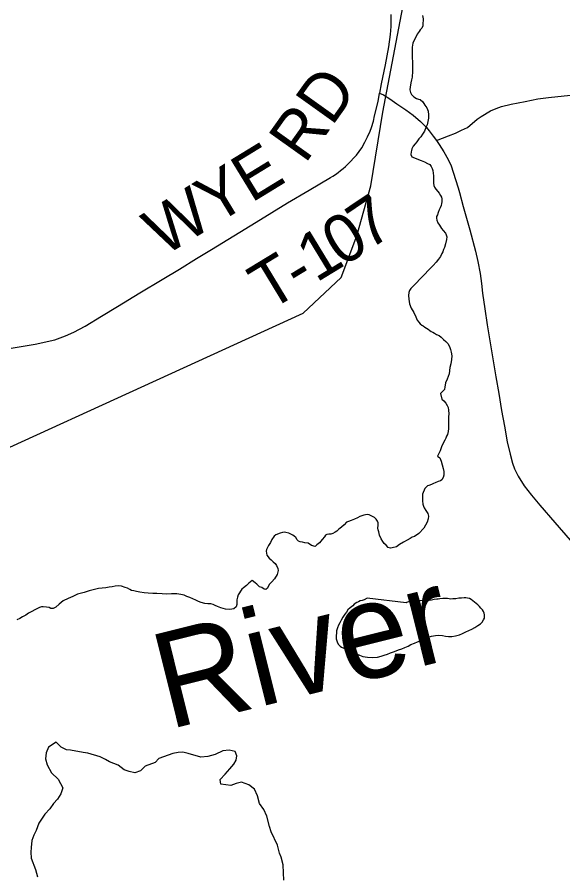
# Model space of a CAD drawing. Extents: x 103424 to 286016, y 38711 to 110967.
# Drawn here: x 125931 to 129380, y 73362 to 78769 of the extents above; entities that cross this region are included whole.
import ezdxf

# ---------------------------------------------------------------- set-up
doc = ezdxf.new("R2010")
doc.units = 0
for name, color, linetype in [('GM_X_County_Road', 7, 'Continuous'), ('GM_X_Major_River', 7, 'Continuous'), ('GM_X_Major_River_Text', 7, 'Continuous'), ('GM_X_Minor_Lake', 7, 'Continuous'), ('GM_X_Rail_Line', 7, 'Continuous'), ('GM_X_Township_Road', 7, 'Continuous'), ('GM_X_Township_Road_Text', 7, 'Continuous')]:
    doc.layers.add(name, color=color, linetype=linetype)

msp = doc.modelspace()

# ---------------------------------------------------------------- linework, layer by layer
at = {"layer": 'GM_X_County_Road'}
for points in [[(128292.5, 78785.5), (128291.8, 78710.8), (128289.3, 78660.5), (128278.7, 78582.9), (128256.6, 78468.5), (128231.2, 78347.8), (128220.8, 78289.4), (128245.2, 78278.6), (128285.2, 78254.5), (128330.5, 78221.8), (128387.7, 78183.4), (128433.5, 78149.9), (128480.5, 78110.3), (128518, 78072.8), (128534.8, 78051.9), (128560.9, 78017.6), (128580.6, 77990.1), (128598.1, 77964.9), (128626.3, 77919.2), (128655.7, 77870.6), (128673.6, 77830.9), (128687.1, 77791.3), (128717.4, 77692.5), (128725.9, 77661.6)], [(128725.9, 77661.6), (128750, 77574), (128792.5, 77427.4), (128828, 77293), (128842.7, 77227.3), (128856.2, 77152.1), (128864.8, 77088.4), (128872.2, 77027.1), (128886.3, 76927.7), (128900.3, 76828.2), (128926.5, 76675.8), (128941.2, 76587.6), (128955.9, 76499.4), (128974.3, 76393.2), (128992.7, 76287), (129009.8, 76188.4), (129027, 76089.7), (129045.7, 76010.1), (129060.9, 75954.1), (129074.8, 75917.8), (129096.4, 75872), (129135.6, 75810.3), (129181.4, 75751.9), (129234.4, 75689.4), (129329.6, 75579.1), (129424.8, 75468.8)]]:
    msp.add_lwpolyline(points, dxfattribs=at)
at = {"layer": 'GM_X_Major_River'}
for points in [[(128492.9, 78779.4), (128497.2, 78759.3), (128497.3, 78747.1), (128495.5, 78731), (128493.7, 78714.8), (128487.8, 78700.6), (128477.8, 78688.4), (128471.9, 78678.2), (128457.9, 78661.9), (128432.3, 78605.1), (128426.6, 78580.8), (128426.9, 78550.5), (128427.3, 78514.2), (128429.7, 78485.9), (128430, 78457.6), (128430.4, 78427.3), (128426.7, 78390.9)], [(128426.7, 78390.9), (128422.9, 78372.7), (128419.1, 78354.5), (128417.2, 78340.3), (128415.3, 78330.2), (128413.5, 78310), (128415.8, 78293.9), (128422, 78281.8), (128438.3, 78265.8), (128454.6, 78255.9), (128466.7, 78252), (128476.9, 78250), (128495.2, 78234), (128507.6, 78214), (128519.9, 78195.9), (128528.2, 78175.8), (128530.5, 78153.6), (128530.7, 78131.4), (128526.9, 78111.1), (128521.1, 78088.9), (128513.2, 78072.6), (128505.4, 78050.3), (128493.5, 78030), (128481.6, 78013.7), (128469.6, 78001.5), (128455.7, 77983.2), (128445.8, 77968.9), (128433.8, 77954.7), (128425.9, 77938.4), (128422, 77928.3), (128420.1, 77918.2), (128418.3, 77902), (128424.5, 77887.9), (128483.3, 77864.3), (128505.7, 77856.4), (128523.9, 77846.5), (128538.2, 77838.6), (128546.4, 77826.5), (128552.6, 77814.5), (128556.8, 77800.4), (128559, 77784.2), (128561.2, 77768.1), (128561.5, 77741.8), (128561.7, 77721.6), (128563.9, 77707.5), (128568.1, 77695.4), (128576.3, 77683.4), (128588.6, 77669.4), (128598.8, 77657.4), (128607.1, 77643.3), (128613.3, 77633.3), (128615.4, 77623.2), (128615.5, 77613.1), (128615.6, 77603), (128611.7, 77592.8), (128609.8, 77580.7), (128603.9, 77566.5), (128598, 77552.3), (128592.2, 77536.1), (128586.3, 77521.9), (128580.3, 77511.7), (128580.5, 77499.6), (128582.6, 77487.5), (128588.9, 77471.4), (128599.2, 77455.4), (128613.5, 77435.3), (128623.8, 77423.3), (128638.1, 77405.2), (128642.3, 77395.2), (128646.5, 77383.1), (128644.6, 77364.9), (128638.9, 77338.6), (128631.1, 77316.3), (128625.2, 77302.1), (128621.3, 77287.9), (128615.4, 77277.8), (128605.5, 77259.5), (128593.6, 77241.2), (128579.6, 77222.9), (128559.7, 77202.5), (128475.9, 77114.8), (128453.9, 77092.3), (128435.9, 77074), (128418, 77055.6), (128410, 77043.4), (128406.1, 77031.3), (128404.3, 77013.1), (128406.6, 76988.8), (128411, 76960.6), (128421.4, 76932.4), (128437.9, 76904.3), (128450.3, 76878.2), (128458.7, 76856), (128468.9, 76844), (128477.1, 76834), (128487.3, 76826), (128497.5, 76820.1), (128507.7, 76812.1), (128517.8, 76806.1), (128528, 76800.2), (128538.2, 76792.2)], [(128538.2, 76792.2), (128548.3, 76786.2), (128558.5, 76780.3), (128568.7, 76774.3), (128580.9, 76766.4), (128597.1, 76760.5), (128611.4, 76748.5), (128625.7, 76734.5), (128640, 76722.5), (128652.2, 76708.5), (128662.6, 76690.4), (128668.8, 76672.3), (128673.1, 76654.2), (128677.4, 76632), (128675.6, 76607.7), (128671.9, 76581.4), (128666.1, 76557.1), (128660.5, 76518.7), (128648.8, 76484.2), (128638.9, 76461.9), (128635.1, 76445.7), (128633.2, 76435.6), (128631.4, 76419.4), (128617.4, 76405.1), (128605.4, 76392.9), (128613.9, 76358.6), (128628.2, 76346.7), (128640.4, 76332.6), (128648.7, 76318.6), (128654.9, 76304.5), (128657.1, 76288.4), (128659.4, 76266.2), (128657.6, 76246), (128655.9, 76217.7), (128656.2, 76193.4), (128656.4, 76173.2), (128654.6, 76155), (128650.8, 76134.8), (128644.9, 76124.6), (128639, 76112.5), (128633.1, 76098.3), (128623.2, 76080), (128613.3, 76057.7), (128603.5, 76031.3), (128593.7, 76011), (128587.8, 75998.8), (128602, 75986.9), (128610.4, 75966.7), (128623, 75920.4), (128627.3, 75902.3), (128627.5, 75878), (128623.7, 75863.8), (128615.7, 75849.6), (128605.7, 75843.5), (128591.6, 75839.3), (128573.5, 75831), (128561.5, 75824.8), (128549.5, 75818.7), (128533.4, 75812.4), (128523.3, 75810.3), (128507.3, 75794), (128491.6, 75757.5), (128491.8, 75737.3), (128491.9, 75727.2), (128492.1, 75717.1), (128494.3, 75694.9), (128498.5, 75682.8), (128502.7, 75672.8), (128513, 75654.7), (128525.3, 75636.6), (128529.5, 75620.5), (128527.7, 75602.3), (128521.9, 75582.1), (128500.1, 75543.5), (128470.2, 75510.8), (128442.2, 75490.4), (128428.1, 75486.2), (128414, 75478), (128396, 75467.7), (128371.9, 75455.3), (128347.8, 75440.9), (128327.8, 75426.6), (128301.6, 75420.3), (128289.5, 75418.1), (128275.3, 75422), (128263, 75436.1), (128250.8, 75448.1), (128242.6, 75460.1), (128232.3, 75476.2), (128221.9, 75500.3), (128215.6, 75520.4), (128211.4, 75532.5), (128211.3, 75544.6), (128213.1, 75562.8), (128212.9, 75576.9), (128208.8, 75589), (128200.5, 75601.1), (128188.3, 75611.1), (128155.8, 75628.9), (128143.6, 75630.8), (128131.6, 75628.7)], [(128131.6, 75628.7), (128121.5, 75626.5), (128109.4, 75622.4), (128097.3, 75618.2), (128081.3, 75610), (128063.2, 75599.7), (128041.1, 75591.4), (128025, 75585.2), (128012.9, 75581), (127997, 75564.7), (127981, 75550.4), (127962.9, 75538.1), (127951, 75525.9), (127941, 75517.7), (127926.9, 75509.5), (127912.8, 75505.3), (127900.7, 75505.2), (127888.6, 75503), (127878.6, 75498.9), (127872.6, 75488.7), (127858.7, 75472.4), (127840.7, 75452.1), (127824.7, 75437.8), (127814.8, 75427.6), (127790.4, 75435.4), (127770.1, 75449.3), (127749.9, 75451.1), (127733.7, 75455), (127719.5, 75456.9), (127709.4, 75460.8), (127701.2, 75470.9), (127692.9, 75484.9), (127682.7, 75492.9), (127672.6, 75498.9), (127648.2, 75512.8), (127629.9, 75516.6), (127619.8, 75518.5), (127607.7, 75516.4), (127593.6, 75512.2), (127565.5, 75501.8), (127555.5, 75493.7), (127541.6, 75471.3), (127531.7, 75453), (127519.8, 75434.7), (127511.9, 75418.5), (127506, 75408.3), (127504.1, 75398.2), (127506.2, 75386.1), (127508.4, 75374), (127522.8, 75354), (127537, 75344), (127549.3, 75332), (127561.5, 75320), (127569.7, 75308), (127578, 75289.9), (127580.2, 75275.8), (127574.4, 75251.4), (127556.6, 75225), (127540.6, 75204.7), (127524.7, 75188.3), (127512.8, 75166), (127502.8, 75155.8), (127492.7, 75159.7), (127476.4, 75169.7), (127462.2, 75173.6), (127445.9, 75189.6), (127435.7, 75199.6), (127417.3, 75213.5), (127395.3, 75197.1), (127381.3, 75182.9), (127361.3, 75166.5), (127351.3, 75158.3), (127327.5, 75123.8), (127323.6, 75107.6), (127319.8, 75091.4), (127319.9, 75077.2), (127320.1, 75063.1), (127314.2, 75046.9), (127300.2, 75034.6), (127276.1, 75030.3), (127247.8, 75032.1), (127217.4, 75041.9), (127197.1, 75049.7), (127182.9, 75055.7), (127170.7, 75061.6), (127154.5, 75065.5), (127136.3, 75067.3), (127118.1, 75069.2), (127093.8, 75075), (127077.5, 75080.9), (127061.3, 75088.8), (127041, 75098.7), (127022.7, 75106.6), (127004.5, 75112.5), (126986.2, 75120.4), (126965.9, 75126.2), (126939.6, 75130), (126907.3, 75129.7), (126875, 75127.3), (126846.7, 75129.1), (126814.4, 75130.8)], [(126814.4, 75130.8), (126788.1, 75132.5), (126759.8, 75134.3), (126733.5, 75136), (126707.3, 75139.8), (126685, 75143.6), (126668.8, 75147.5), (126654.6, 75151.4), (126642.4, 75157.3), (126628.2, 75165.3), (126614, 75169.2), (126591.7, 75177), (126573.5, 75178.9), (126551.3, 75178.7), (126531.1, 75174.4), (126513, 75172.2), (126490.8, 75167.9), (126468.6, 75165.7), (126446.4, 75163.5), (126386, 75148.7), (126355.8, 75138.3), (126313.5, 75127.8), (126283.4, 75113.4), (126253.3, 75098.9), (126223.1, 75084.5), (126197.1, 75064), (126175.1, 75045.6), (126159.1, 75037.4), (126144.9, 75037.2), (126132.7, 75043.2), (126116.6, 75045), (126096.3, 75046.9), (126084.2, 75046.8), (126072.2, 75042.6), (126060.1, 75036.4), (126044, 75028.2), (126024, 75017.9), (126003.9, 75007.6), (125985.9, 74995.3), (125965.8, 74985), (125947.8, 74972.7), (125929.7, 74964.4)]]:
    msp.add_lwpolyline(points, dxfattribs=at)
at = {"layer": 'GM_X_Minor_Lake'}
for points in [[(127977.7, 74962.6), (127969.8, 74946.3), (127961.9, 74932.1), (127956, 74913.9), (127950.2, 74895.6), (127948.4, 74879.5), (127946.5, 74869.3), (127946.6, 74855.2), (127946.7, 74845.1), (127953, 74827), (127959.3, 74810.9), (127971.5, 74798.9), (127981.7, 74792.9), (127995.9, 74787), (128006, 74783.1), (128016.2, 74777.1), (128030.4, 74771.2), (128079.1, 74749.4), (128095.4, 74741.5), (128115.7, 74733.7), (128144, 74729.9), (128174.3, 74728.2), (128208.6, 74730.5), (128230.8, 74736.8), (128250.9, 74743.1), (128271, 74749.3), (128291.1, 74757.6), (128309.2, 74763.9), (128325.3, 74770.1), (128341.4, 74776.3), (128361.5, 74782.6), (128381.6, 74790.8), (128401.7, 74799.1), (128419.8, 74809.4), (128441.9, 74817.7), (128460, 74826), (128478.1, 74832.2), (128494.1, 74840.4), (128512.2, 74848.7), (128530.3, 74854.9), (128550.4, 74861.2), (128574.6, 74865.5), (128596.8, 74867.7), (128619.1, 74865.9), (128637.3, 74862.1), (128657.5, 74860.2), (128677.7, 74860.4), (128701.9, 74864.7), (128726.1, 74871), (128746.2, 74879.3), (128766.2, 74889.6), (128786.3, 74897.9), (128804.4, 74906.1), (128822.5, 74916.4), (128842.5, 74928.7), (128858.6, 74939), (128870.5, 74951.2), (128878.5, 74965.5), (128884.4, 74975.6), (128884.3, 74987.7), (128884.1, 74997.8), (128882, 75007.9), (128877.8, 75018), (128871.7, 75028), (128861.5, 75038), (128853.2, 75050.1), (128843, 75060), (128800.2, 75094), (128790, 75099.9), (128775.9, 75101.8), (128765.8, 75103.7), (128755.7, 75103.6), (128739.5, 75101.4), (128721.4, 75101.3), (128703.2, 75097), (128685.1, 75096.9), (128670.9, 75096.7), (128650.7, 75100.6), (128638.6, 75100.4), (128620.4, 75100.2), (128602.2, 75098.1), (128592.2, 75095.9), (128582.1, 75095.8), (128565.9, 75093.6), (128549.8, 75089.4), (128533.7, 75087.3), (128513.5, 75087.1), (128491.3, 75086.9), (128479.2, 75084.7), (128469.1, 75084.6), (128457, 75084.5), (128438.8, 75084.3), (128426.7, 75082.2), (128410.6, 75080), (128392.5, 75073.7), (128389.6, 75073)], [(128143.7, 75101.6), (128123.6, 75091.3), (128111.6, 75087.1), (128099.5, 75085), (128087.4, 75078.8), (128077.4, 75074.7), (128061.3, 75064.4), (128051.4, 75054.2), (128035.3, 75041.9), (128021.4, 75027.6), (128011.4, 75013.4), (128001.5, 75001.2), (127989.6, 74982.9), (127977.7, 74962.6)], [(128389.6, 75073), (128143.7, 75101.6)], [(127616.2, 73321.9), (127613.6, 73368), (127611.2, 73418.4), (127598.8, 73466.7), (127588.5, 73492.9), (127576.1, 73543.3), (127537.2, 73627.8), (127524.9, 73660), (127508.3, 73726.4), (127489.9, 73768.7), (127463.4, 73806.8), (127451, 73855.2), (127430.6, 73897.4), (127396.2, 73923.4), (127349.8, 73941.3), (127315.6, 73932.9), (127281.5, 73920.6), (127249.2, 73924.4), (127219, 73928.2), (127214.8, 73958.5), (127244.7, 73991), (127274.7, 74025.5), (127300.6, 74053.9), (127314.5, 74080.2), (127318.4, 74106.5), (127308.1, 74134.7), (127271.8, 74142.5), (127231.6, 74138.2), (127183.4, 74115.7), (127135.2, 74103.2), (127091, 74098.9), (127012.3, 74122.6), (126978, 74130.4), (126947.9, 74128.2), (126915.7, 74121.9), (126827.4, 74091), (126803.4, 74064.6), (126741.2, 74042), (126711.2, 74011.5), (126675.1, 73999.2), (126638.8, 74007), (126606.5, 74018.9), (126570, 74048.9), (126515.5, 74068.7), (126489.2, 74084.7), (126456.9, 74100.6), (126378.3, 74124.3), (126348, 74128.1), (126269.4, 74143.7), (126243.3, 74145.5), (126208.9, 74161.5), (126178.5, 74193.5), (126130.4, 74160.9), (126114.6, 74126.5), (126110.8, 74088.1), (126121.2, 74049.9), (126147.7, 73999.6), (126190.3, 73959.5), (126204.5, 73931.4), (126220.8, 73905.3), (126207, 73866.8), (126187.1, 73834.4), (126161.2, 73806), (126137.3, 73771.5), (126105.3, 73739), (126067.5, 73682.3), (126051.7, 73635.7), (126037.8, 73605.4), (126024, 73573), (126020.3, 73528.6), (126018.5, 73498.3), (126020.8, 73462), (126047.5, 73389.5), (126059.9, 73343.2)]]:
    msp.add_lwpolyline(points, dxfattribs=at)
at = {"layer": 'GM_X_Rail_Line'}
msp.add_lwpolyline([(124786.7, 75555.1), (127738.5, 76901), (127978.1, 77126.6), (128076.8, 77389.8), (128166, 77704.7), (128241.2, 78169.9), (128368.1, 78832.6)], dxfattribs=at)
at = {"layer": 'GM_X_Township_Road'}
for points in [[(125893, 76680.4), (126044.4, 76704.6), (126169.2, 76732.3), (126237.3, 76757.8), (126288.8, 76780.3), (126360.8, 76819.3), (126463.4, 76881), (126566, 76942.6), (126707.1, 77028.3), (126848.2, 77113.9), (126956.1, 77179.4), (127064, 77244.9), (127159.9, 77303.2), (127300.7, 77389.3), (127441.5, 77475.4), (127540.5, 77536), (127639.5, 77596.5), (127775.5, 77676.5), (127911.6, 77756.5), (127925.7, 77765.5), (127942.5, 77776.7), (127958.9, 77788.4), (127974.8, 77800.8), (127990.4, 77813.7), (128005.2, 77827.1), (128019.9, 77841.1), (128076.5, 77898.7), (128108.5, 77944.1), (128127.9, 77980), (128135.9, 77997), (128145.4, 78014), (128161.9, 78049.4), (128169.9, 78073.3), (128181.9, 78112.8), (128190.3, 78146.2), (128211.6, 78236.9), (128220.8, 78289.4)], [(128580.6, 77990.1), (128657.1, 78020), (128700.8, 78036), (128740, 78055.2), (128776.4, 78072.9), (128837.9, 78124.7), (128863.5, 78142.6), (128922, 78177.1), (128958.9, 78192.7), (128991.7, 78205), (129053.4, 78220.4), (129140.2, 78237.3), (129221.3, 78252.7), (129288.3, 78262.9), (129428.5, 78277)]]:
    msp.add_lwpolyline(points, dxfattribs=at)

# ---------------------------------------------------------------- texts
at = {"layer": 'GM_X_Major_River_Text'}
msp.add_text('River', height=604.14, rotation=14.0088, dxfattribs=at).set_placement((126886.6, 74271.3))
at = {"layer": 'GM_X_Township_Road_Text'}
for s, height, rotation, p in [('RD', 301.87, 54.5215, (127750.1, 77837.6)), ('WYE', 301.87, 31.4289, (126855.1, 77254.6)), ('7', 301.9, 33.8781, (128149.7, 77292.8)), ('0', 301.9, 31.6255, (127980.5, 77188.3)), ('1', 301.9, 31.3308, (127820.2, 77090.8)), ('T', 301.9, 31.2467, (127520.8, 76909)), ('-', 301.9, 31.2661, (127714, 77026.2))]:
    msp.add_text(s, height=height, rotation=rotation, dxfattribs=at).set_placement(p)

doc.saveas('drawing.dxf')
